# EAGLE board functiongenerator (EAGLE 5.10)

Size 100 x 80 mm. Coordinates in mm from the lower left corner, seen from the top.
Outline: 0,0 100,0 100,80 0,80 0,0
Copper layers (1*16): Top 0.035mm / dielectric 1.5mm / Bottom 0.035mm
Design rules "default": minimum track width 10mil, minimum drill 24mil, track to track 8mil, track to pad 8mil, pad to pad 8mil, via to via 8mil, smd to smd 8mil, copper to edge 40mil, drill to drill 8mil, minimum pad ring 10mil, minimum via ring 8mil, stop-mask expansion 4mil, vias tented up to drill 0mil, thermal gap 10mil

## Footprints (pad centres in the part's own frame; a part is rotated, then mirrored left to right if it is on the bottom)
B-DIL = drill 0.813 round: + -2.54,-3.81 | drill 0.813 octagon: - 2.54,-3.81; AC1 2.54,3.81; AC2 -2.54,3.81
C025-024X044 = drill 0.813 octagon: 1 -1.27,0; 2 1.27,0
E2,5-7 = drill 0.813 pad 1.6 round: + -1.27,0 | drill 0.813 pad 1.6 octagon: - 1.27,0
E2-5 = drill 0.813 pad 1.27 round: + -1.016,0 | drill 0.813 pad 1.27 octagon: - 1.016,0
C025-030X050 = drill 0.813 octagon: 1 -1.27,0; 2 1.27,0
DO35-10 = drill 0.813 long: A 5.08,0; C -5.08,0
SH22,5A = drill 1.321 pad 2.54 long: 1 -11.252,0; 2 11.252,0
DIL16 = drill 0.813 long: 1 -8.89,-3.81; 2 -6.35,-3.81; 3 -3.81,-3.81; 4 -1.27,-3.81; 5 1.27,-3.81; 6 3.81,-3.81; 7 6.35,-3.81; 8 8.89,-3.81; 9 8.89,3.81; 10 6.35,3.81; 11 3.81,3.81; 12 1.27,3.81; 13 -1.27,3.81; 14 -3.81,3.81; 15 -6.35,3.81; 16 -8.89,3.81
78XXL = drill 1.016 long: GND 0,-3.81; IN -2.54,-3.81; OUT 2.54,-3.81 | hole 3.302: 0,11.176
79XXL = drill 1.016 long: GND -2.54,-3.81; IN 0,-3.81; OUT 2.54,-3.81 | hole 3.302: 0,11.176
DIL08 = drill 0.813 pad 1.27 round: 1 -3.81,-3.81; 2 -1.27,-3.81; 3 1.27,-3.81; 4 3.81,-3.81; 5 3.81,3.81; 6 1.27,3.81; 7 -1.27,3.81; 8 -3.81,3.81
3RP/1610N = drill 1.2 pad 2.184 round: 1 -5,0; 2 0,0; 3 5,0
0207/10 = drill 0.813 octagon: 1 -5.08,0; 2 5.08,0
320-916 = drill 2.007 long: 1 0,4.013; 2 0,0; 3 0,-4.013
50-3POLE30 = drill 0.7 pad 1.2 round: 1 6.207,-1.342; 2 4.704,-4.265; 3 1.941,-6.046; 4 -1.342,-6.207; 5 -4.265,-4.704; 6 -6.046,-1.941; 7 -6.207,1.342; 8 -4.704,4.265; 9 -1.941,6.046; 10 1.342,6.207; 11 4.265,4.704; 12 6.046,1.941; C1 0.825,-1.429; C2 -1.65,0; C3 0.825,1.429
CK102X06 = drill 1.321 octagon: A -2.87,-2.87; A1 -2.845,-10.617; A2 -7.772,-7.772; A3 -10.617,-2.845; A4 -10.617,2.845; A5 -7.772,7.772; A6 -2.845,10.617; C 2.87,2.87; C1 2.845,10.617; C2 7.772,7.772; C3 10.617,2.845; C4 10.617,-2.845; C5 7.772,-7.772; C6 2.845,-10.617
ELMA-01-2X3 = drill 1.3 pad 2.184 round: 1A -0.51,8.334; 1B 0.51,-8.334; 2A 6.963,4.609; 2B -6.963,-4.609; 3A 7.473,-3.726; 3B -7.473,3.726 | drill 1.5 pad 2.54 round: A -2.652,2.652; B 2.652,-2.652
TO220 = drill 1.118 long: 1 -2.54,-6.35; 2 0,-6.35; 3 2.54,-6.35 | hole 3.302: 0,11.176
BU-SMA-G = drill 1.27 round: 1 0,0 | drill 1.778 round: 2 -2.55,2.55; 3 2.55,2.55; 4 2.55,-2.55; 5 -2.55,-2.55

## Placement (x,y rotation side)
B1  [B-DIL]  not placed on the board
B2  [B-DIL]  not placed on the board
C1  [C025-024X044]  not placed on the board
C2  [C025-024X044]  not placed on the board
C3  [C025-024X044]  not placed on the board
C4  [C025-024X044]  not placed on the board
C5  [E2,5-7]  not placed on the board
C6  [E2,5-7]  not placed on the board
C7  10u  [E2-5]  not placed on the board
C8  1n  [C025-030X050]  not placed on the board
C9  10n  [C025-030X050]  not placed on the board
C10  100n  [C025-030X050]  not placed on the board
C11  1u  [C025-030X050]  not placed on the board
C12  10u  [E2,5-7]  not placed on the board
C13  100u  [E2,5-7]  not placed on the board
C14  100n  [C025-024X044]  not placed on the board
C15  4p7  [C025-024X044]  not placed on the board
C16  22p  [C025-024X044]  not placed on the board
C17  22p  [C025-024X044]  not placed on the board
C18  470p  [C025-024X044]  not placed on the board
C19  4n7  [C025-024X044]  not placed on the board
C20  47n  [C025-024X044]  not placed on the board
C21  68p  [C025-024X044]  not placed on the board
C22  4'7  [C025-024X044]  not placed on the board
C23  22u  [C025-024X044]  not placed on the board
C24  33p  [C025-024X044]  not placed on the board
D1  1N4148  [DO35-10]  not placed on the board
D2  1N4148  [DO35-10]  not placed on the board
F1  [SH22,5A]  not placed on the board
IC1  [DIL16]  not placed on the board
IC2  7824  [78XXL]  not placed on the board
IC3  7924  [79XXL]  not placed on the board
IC4  TL082P  [DIL08]  not placed on the board
R1  10k  [3RP/1610N]  not placed on the board
R2  8k2  [0207/10]  not placed on the board
R3  1k  [0207/10]  not placed on the board
R4  2M  [3RP/1610N]  not placed on the board
R5  560  [0207/10]  not placed on the board
R6  50k  [3RP/1610N]  not placed on the board
R7  8k2  [0207/10]  not placed on the board
R8  330  [0207/10]  not placed on the board
R9  330  [0207/10]  not placed on the board
R10  33k  [0207/10]  not placed on the board
R11  33k  [0207/10]  not placed on the board
R12  100  [0207/10]  not placed on the board
R13  10k  [0207/10]  not placed on the board
R14  10k  [0207/10]  not placed on the board
R15  100k  [0207/10]  not placed on the board
R16  100k  [0207/10]  not placed on the board
R17  22k  [0207/10]  not placed on the board
R18  100k  [3RP/1610N]  not placed on the board
R19  4k7  [0207/10]  not placed on the board
R20  220  [0207/10]  not placed on the board
R21  4k7  [0207/10]  not placed on the board
R22  22  [0207/10]  not placed on the board
R23  2,2  [0207/10]  not placed on the board
R24  15k  [0207/10]  not placed on the board
R25  47  [0207/10]  not placed on the board
R26  500  [3RP/1610N]  not placed on the board
R27  22k  [0207/10]  not placed on the board
R28  100k  [0207/10]  not placed on the board
R29  100k  [0207/10]  not placed on the board
R30  240k  [0207/10]  not placed on the board
S1  [320-916]  not placed on the board
S2  Waveform  [50-3POLE30]  not placed on the board
S3  [CK102X06]  not placed on the board
S4  [ELMA-01-2X3]  not placed on the board
T1  BC558  [TO220]  not placed on the board
T2  BC548  [TO220]  not placed on the board
X1  BNC  [BU-SMA-G]  not placed on the board
X2  BNC  [BU-SMA-G]  not placed on the board
X3  BNC  [BU-SMA-G]  not placed on the board

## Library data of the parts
B1 B2 = rectifier
C1-C24 R2 R3 R5 R7-R17 R19-R25 R27-R30 = rcl
D1 D2 = diode
F1 = fuse
IC1 = exar
IC2 IC3 = v-reg
IC4 = linear
R1 R4 R6 R18 R26 = pot
S1-S4 = switch
T1 T2 = transistor
X1-X3 = con-coax

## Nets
+9V: C4.1 C6.+ IC1.4 IC2.OUT IC4.8 R2.2 R10.2 R18.3 R28.1 R29.1 T2.2
+24V: C17.1 R19.1 S2.C3
-9V: C3.2 C5.- IC3.OUT IC4.4 R11.1 R30.1 T1.2
GND: B1.- B2.- C1.2 C2.1 C3.1 C4.2 C5.+ C6.- C7.- C14.2 C18.1 C19.1 C20.1 C24.2 IC1.12 IC2.GND IC3.GND IC4.5 R1.1 R4.1 R4.2 R7.1 R15.1 R20.1 R22.1 R23.1 X1.3 X1.4 X1.5 X2.3 X2.4 X2.5 X3.3 X3.4 X3.5
N$1: B1.+ C1.1 IC2.IN
N$2: B2.+ C2.2 IC3.IN
N$3: S1.1
N$5: R1.3 R2.1
N$6: B1.AC1
N$7: C7.+ IC1.1 R1.2
N$8: D2.C R11.2 T1.1
N$9: B1.AC2
N$10: B2.AC1
N$11: B2.AC2
N$12: F1.2 S1.2
N$13: F1.1
N$14: IC1.6 S3.A
N$15: C8.1 S3.A1
N$16: C9.1 S3.A2
N$17: C10.1 S3.A3
N$18: C11.1 S3.A4
N$19: C12.+ S3.A5
N$20: C13.+ S3.A6
N$21: C8.2 C9.2 C10.2 C11.2 C12.- C13.- IC1.5
N$22: IC1.7 R3.2
N$23: R3.1 R4.3
N$24: R9.1 T1.3
N$25: IC1.11 S2.C2
N$26: IC1.3 R6.1
N$27: R6.2 R6.3 R7.2
N$28: D1.A R10.1 T2.1
N$29: D1.C D2.A R12.2
N$30: C23.1 R5.1 R8.1 R9.2 R13.2 R25.1
N$31: R8.2 T2.3
N$32: R18.1 R30.2
N$33: IC4.7 R12.1
N$34: IC4.6 R13.1 R14.2
N$36: C15.2 IC4.1 R14.1 R17.2
N$37: C15.1 C16.2 IC4.2 R17.1 R21.2
N$38: C14.1 IC4.3 R15.2 R16.2
N$39: R16.1 R18.2
N$40: C18.2 R20.2 S4.1B
N$41: C16.1 C17.2 R19.2 R21.1 S4.B
N$42: C19.2 R22.2 S4.2B
N$43: C21.2 IC1.2 R24.2 S2.9
N$44: C20.2 R23.2 S4.3B
N$45: C21.1 R24.1 S2.10 S2.11
N$46: C22.1 C24.1 R27.1 S2.12
N$47: R26.3 S2.1
N$48: X1.2 X2.2 X3.2
N$49: C23.2 X1.1
N$50: R5.2 X2.1
N$51: R25.2 X3.1
N$52: IC1.13 R26.1 R26.2
N$53: IC1.14 S2.C1
N$54: IC1.9 S2.7
N$56: C22.2 R27.2 R28.2 R29.2 S2.8

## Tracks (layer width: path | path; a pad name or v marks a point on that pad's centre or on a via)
+9V  (10 unrouted)
+24V  (2 unrouted)
-9V  (6 unrouted)
GND  (34 unrouted)
N$1  (2 unrouted)
N$2  (2 unrouted)
N$5  (1 unrouted)
N$7  (2 unrouted)
N$8  (2 unrouted)
N$12  (1 unrouted)
N$14  (1 unrouted)
N$15  (1 unrouted)
N$16  (1 unrouted)
N$17  (1 unrouted)
N$18  (1 unrouted)
N$19  (1 unrouted)
N$20  (1 unrouted)
N$21  (6 unrouted)
N$22  (1 unrouted)
N$23  (1 unrouted)
N$24  (1 unrouted)
N$25  (1 unrouted)
N$26  (1 unrouted)
N$27  (2 unrouted)
N$28  (2 unrouted)
N$29  (2 unrouted)
N$30  (5 unrouted)
N$31  (1 unrouted)
N$32  (1 unrouted)
N$33  (1 unrouted)
N$34  (2 unrouted)
N$36  (3 unrouted)
N$37  (4 unrouted)
N$38  (3 unrouted)
N$39  (1 unrouted)
N$40  (2 unrouted)
N$41  (4 unrouted)
N$42  (2 unrouted)
N$43  (3 unrouted)
N$44  (2 unrouted)
N$45  (3 unrouted)
N$46  (3 unrouted)
N$47  (1 unrouted)
N$48  (2 unrouted)
N$49  (1 unrouted)
N$50  (1 unrouted)
N$51  (1 unrouted)
N$52  (2 unrouted)
N$53  (1 unrouted)
N$54  (1 unrouted)
N$56  (4 unrouted)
